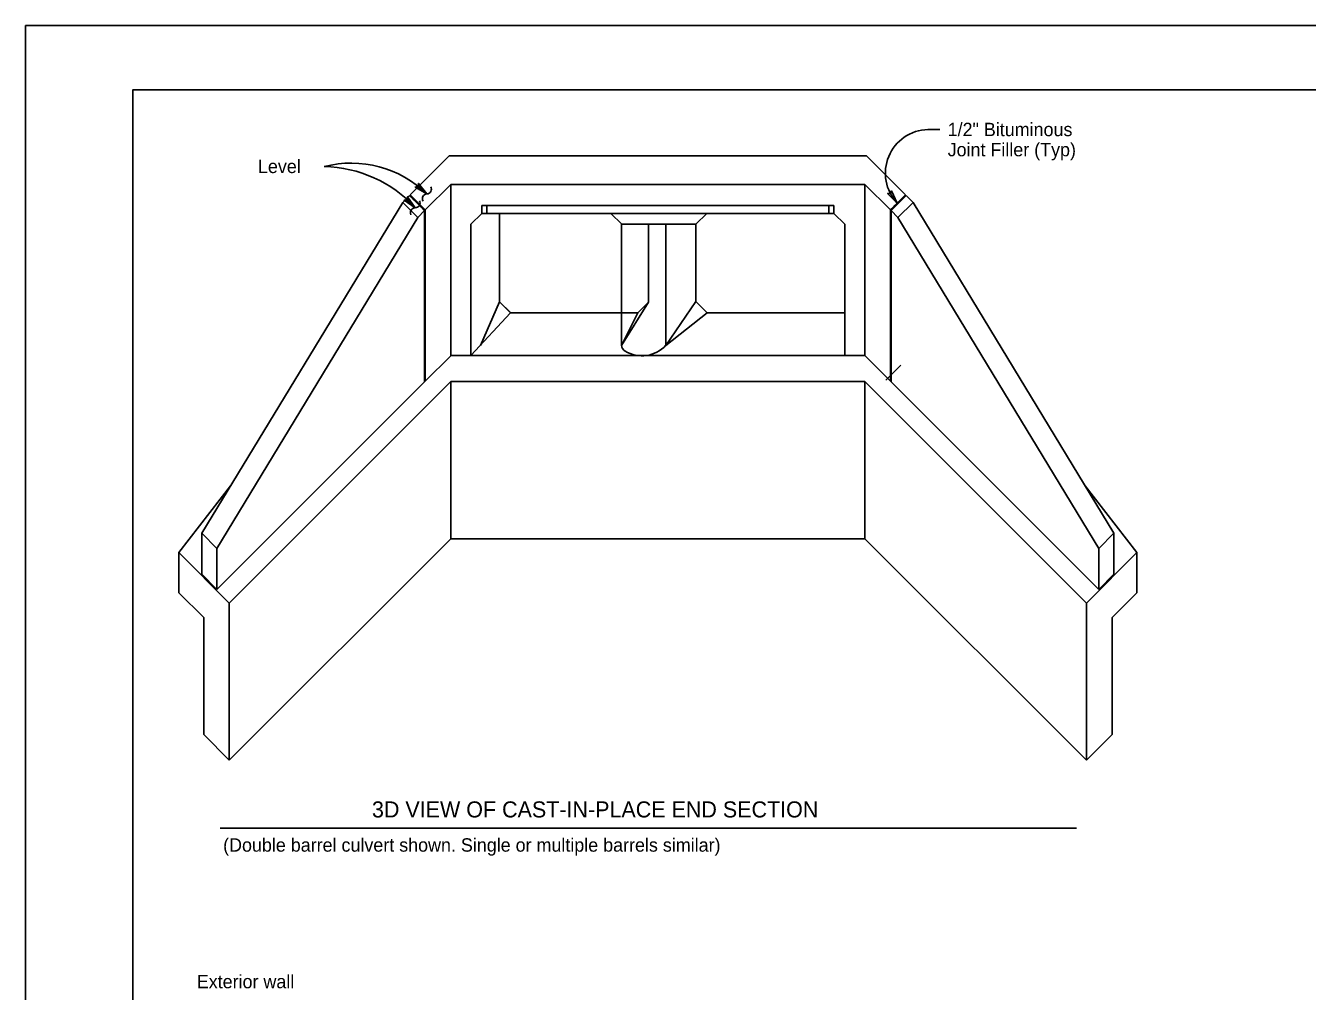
# Model space of a CAD drawing. Extents: x 0 to 2.83, y -0.03 to 1.83.
# Drawn here: x 0 to 1.247, y 0.894 to 1.833 of the extents above; entities that cross this region are included whole.
import ezdxf

# ---------------------------------------------------------------- set-up
doc = ezdxf.new("R2010")
doc.units = 0
for name, color, linetype in [('50', 7, 'Continuous'), ('54', 7, 'Continuous'), ('55', 7, 'Continuous'), ('57', 7, 'Continuous'), ('63', 7, 'Continuous'), ('Default', 7, 'Continuous')]:
    doc.layers.add(name, color=color, linetype=linetype)

msp = doc.modelspace()

# ---------------------------------------------------------------- linework, layer by layer
at = {"layer": '50'}
for p, q in [((0.4119, 1.7067), (0.374, 1.6688)), ((0.8181, 1.7067), (0.856, 1.6688)), ((0.4136, 1.6789), (0.3887, 1.6541)), ((0.8164, 1.6789), (0.8413, 1.6541)), ((0.3733, 1.6682), (0.3668, 1.6613)), ((0.3815, 1.6466), (0.3668, 1.6613)), ((0.3881, 1.6534), (0.3733, 1.6682)), ((0.3881, 1.6534), (0.3733, 1.6682)), ((0.3884, 1.6538), (0.3737, 1.6685)), ((0.3887, 1.6541), (0.374, 1.6688)), ((0.3887, 1.6541), (0.374, 1.6688)), ((0.7863, 1.6585), (0.4437, 1.6585)), ((0.4437, 1.6585), (0.4437, 1.6507)), ((0.4487, 1.6585), (0.4487, 1.6507)), ((0.7812, 1.6585), (0.7812, 1.6507)), ((0.7863, 1.6585), (0.7863, 1.6507)), ((0.8413, 1.6541), (0.856, 1.6688)), ((0.8413, 1.6541), (0.856, 1.6688)), ((0.8419, 1.6534), (0.8566, 1.6682)), ((0.8419, 1.6534), (0.8566, 1.6682)), ((0.8484, 1.6466), (0.8632, 1.6613)), ((0.8566, 1.6682), (0.8632, 1.6613)), ((0.3881, 1.6534), (0.3815, 1.6466)), ((0.4331, 1.6401), (0.4437, 1.6507)), ((0.5798, 1.6401), (0.5692, 1.6507)), ((0.652, 1.6401), (0.6626, 1.6507)), ((0.7968, 1.6401), (0.7863, 1.6507)), ((0.8419, 1.6534), (0.8484, 1.6466)), ((0.4611, 1.5645), (0.4425, 1.5223)), ((0.4611, 1.5645), (0.4716, 1.5541)), ((0.4717, 1.5539), (0.4611, 1.5645)), ((0.5956, 1.5539), (0.6059, 1.5643)), ((0.6629, 1.5539), (0.652, 1.5649)), ((0.4136, 1.5122), (0.3887, 1.4873)), ((0.8164, 1.5123), (0.8413, 1.4874)), ((0.8368, 1.4884), (0.8515, 1.5031)), ((0.3881, 1.4868), (0.1861, 1.2848)), ((0.8419, 1.4868), (1.0438, 1.2848)), ((0.1861, 1.3247), (0.1714, 1.3395)), ((0.1861, 1.3247), (0.1714, 1.3395)), ((1.0438, 1.3248), (1.0586, 1.3395)), ((0.1861, 1.2848), (0.1714, 1.2996))]:
    msp.add_line(p, q, dxfattribs=at)
for points in [[(0.3765, 1.6662), (0.3744, 1.6684), (0.3738, 1.6678), (0.3759, 1.6657)], [(0.3787, 1.6641), (0.3765, 1.6662), (0.3759, 1.6657), (0.3781, 1.6635)], [(0.3862, 1.6566), (0.384, 1.6587), (0.3834, 1.6581), (0.3856, 1.656)], [(0.8444, 1.656), (0.8465, 1.6581), (0.8459, 1.6587), (0.8438, 1.6565)], [(0.8519, 1.6635), (0.854, 1.6656), (0.8534, 1.6662), (0.8513, 1.6641)], [(0.854, 1.6656), (0.8562, 1.6678), (0.8556, 1.6684), (0.8534, 1.6662)], [(0.3883, 1.6544), (0.3862, 1.6566), (0.3856, 1.656), (0.3877, 1.6538)], [(0.8422, 1.6538), (0.8444, 1.656), (0.8438, 1.6565), (0.8416, 1.6544)]]:
    msp.add_lwpolyline(points, close=True, dxfattribs=at)
at = {"layer": '54'}
msp.add_lwpolyline([(0.8479, 1.6607), (0.8384, 1.6699), (0.8412, 1.67), (0.8424, 1.6725)], close=True, dxfattribs=at)
at = {"layer": '55'}
for points in [[(0.3903, 1.6696), (0.379, 1.6763), (0.3811, 1.6769), (0.3881, 1.6716), (0.3818, 1.6777), (0.3821, 1.6799), (0.3903, 1.6696)], [(0.3863, 1.6723), (0.3813, 1.6763), (0.3803, 1.676), (0.3892, 1.6705), (0.3825, 1.6786), (0.3824, 1.6775), (0.3869, 1.6734)], [(0.379, 1.6561), (0.3682, 1.6635), (0.3703, 1.664), (0.3769, 1.6582), (0.371, 1.6648), (0.3715, 1.6669), (0.379, 1.6561)], [(0.3752, 1.6591), (0.3705, 1.6634), (0.3694, 1.6632), (0.378, 1.6571), (0.3718, 1.6656), (0.3716, 1.6645), (0.3758, 1.6601)]]:
    msp.add_lwpolyline(points, dxfattribs=at)
for centre, radius, start, end in [((0.3171, 1.5953), 0.1043, 45.4286, 104.8009), ((0.2881, 1.5729), 0.1233, 42.4819, 88.898), ((0.39, 1.6743), 0.0047, 273.7928, 30.1989), ((0.379, 1.6608), 0.0047, 270.0562, 26.4623), ((0.3906, 1.6649), 0.0047, 93.7928, 210.1989), ((0.379, 1.6514), 0.0047, 90.0562, 206.4623)]:
    msp.add_arc(centre, radius, start, end, dxfattribs=at)
at = {"layer": '63'}
for p, q in [((0, 0), (0, 1.8333)), ((0, 1.8333), (2.8333, 1.8333))]:
    msp.add_line(p, q, dxfattribs=at)
msp.add_lwpolyline([(2.7292, 1.7708), (0.1042, 1.7708), (0.1042, 0.0624), (2.7292, 0.0624)], close=True, dxfattribs=at)
at = {"layer": 'Default'}
for p, q in [((0.8894, 1.7324), (0.8777, 1.7324)), ((0.4119, 1.7067), (0.8181, 1.7067)), ((0.4136, 1.6789), (0.8164, 1.6789)), ((0.4136, 1.6789), (0.4136, 1.5122)), ((0.8164, 1.6789), (0.8164, 1.5122)), ((0.3668, 1.6613), (0.1714, 1.3395)), ((0.8632, 1.6613), (1.0586, 1.3395)), ((0.3815, 1.6466), (0.1861, 1.3247)), ((0.3881, 1.6534), (0.3881, 1.4868)), ((0.3887, 1.6541), (0.3887, 1.4874)), ((0.4437, 1.6507), (0.5692, 1.6507)), ((0.4611, 1.6507), (0.4611, 1.5645)), ((0.5692, 1.6507), (0.7863, 1.6507)), ((0.8413, 1.6541), (0.8413, 1.4874)), ((0.8419, 1.6534), (0.8419, 1.4868)), ((0.8484, 1.6466), (1.0438, 1.3248)), ((0.4331, 1.6401), (0.4331, 1.5123)), ((0.5796, 1.6401), (0.5796, 1.5223)), ((0.5796, 1.6401), (0.652, 1.6401)), ((0.6059, 1.5643), (0.6059, 1.6401)), ((0.6227, 1.6401), (0.6227, 1.5223)), ((0.652, 1.6401), (0.652, 1.5649)), ((0.7968, 1.6401), (0.7968, 1.5123)), ((0.5796, 1.5223), (0.6059, 1.5643)), ((0.6228, 1.5223), (0.652, 1.5649)), ((0.4331, 1.5123), (0.4717, 1.5539)), ((0.4717, 1.5539), (0.5798, 1.5539)), ((0.5796, 1.5223), (0.5956, 1.5539)), ((0.5798, 1.5539), (0.5956, 1.5539)), ((0.6629, 1.5539), (0.6227, 1.5223)), ((0.6629, 1.5539), (0.7968, 1.5539)), ((0.4136, 1.5123), (0.8164, 1.5123)), ((0.4136, 1.5123), (0.8164, 1.5123)), ((0.4136, 1.487), (0.1981, 1.2715)), ((0.4136, 1.487), (0.8164, 1.487)), ((0.4136, 1.487), (0.4136, 1.3342)), ((0.8164, 1.487), (1.0319, 1.2715)), ((0.8164, 1.487), (0.8164, 1.3342)), ((0.149, 1.3206), (0.1994, 1.3855)), ((1.081, 1.3206), (1.0306, 1.3855)), ((0.1714, 1.3395), (0.1714, 1.2996)), ((0.4136, 1.3342), (0.1981, 1.1187)), ((0.4136, 1.3342), (0.8164, 1.3342)), ((0.8164, 1.3342), (1.0319, 1.1187)), ((1.0586, 1.3395), (1.0586, 1.2996)), ((0.1861, 1.3247), (0.1861, 1.2848)), ((1.0438, 1.3248), (1.0438, 1.2848)), ((0.1981, 1.2715), (0.149, 1.3206)), ((0.149, 1.3206), (0.149, 1.2816)), ((1.0319, 1.2715), (1.081, 1.3206)), ((1.081, 1.3206), (1.081, 1.2816)), ((1.0438, 1.2848), (1.0586, 1.2996)), ((0.1732, 1.2574), (0.149, 1.2816)), ((1.0568, 1.2574), (1.081, 1.2816)), ((0.1981, 1.2715), (0.1981, 1.1187)), ((1.0319, 1.2715), (1.0319, 1.1187)), ((0.1732, 1.2574), (0.1732, 1.1436)), ((1.0568, 1.2574), (1.0568, 1.1436)), ((0.1981, 1.1187), (0.1732, 1.1436)), ((1.0319, 1.1187), (1.0568, 1.1436)), ((0.1892, 1.0525), (1.0221, 1.0525))]:
    msp.add_line(p, q, dxfattribs=at)
for centre, radius, start, end in [((0.8788, 1.6898), 0.0425, 91.5605, 223.2807), ((0.5867, 1.5228), 0.00707, 183.8509, 239.9419), ((0.5995, 1.5435), 0.0314, 238.6242, 317.5984)]:
    msp.add_arc(centre, radius, start, end, dxfattribs=at)

# ---------------------------------------------------------------- texts
at = {"layer": '57'}
for s, height, p in [('1/2" Bituminous', 0.013021, (0.8969, 1.7258)), ('Joint Filler (Typ)', 0.013021, (0.8969, 1.7062)), ('Level', 0.01302, (0.226, 1.6899)), ('(Double barrel culvert shown. Single or multiple barrels similar)', 0.013021, (0.1921, 1.0297)), ('Exterior wall ', 0.013021, (0.1665, 0.8968))]:
    msp.add_text(s, height=height, dxfattribs=at).set_placement(p)
at = {"layer": 'Default'}
msp.add_text('3D VIEW OF CAST-IN-PLACE END SECTION', height=0.015625, dxfattribs=at).set_placement((0.3369, 1.063))

doc.saveas('drawing.dxf')
